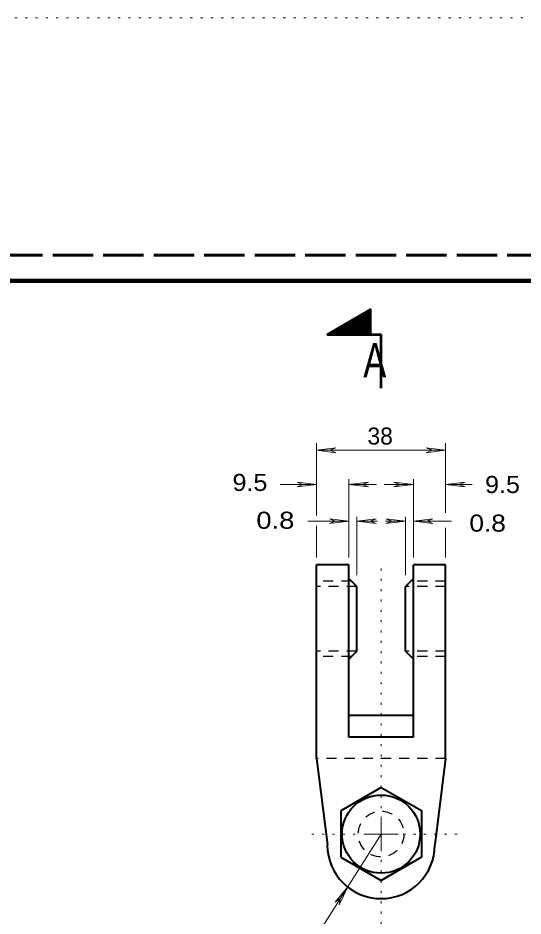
# Model space of a CAD drawing. Extents: x 312583 to 312854, y 144419 to 144597.
# Drawn here: x 312663.9 to 312686.4, y 144556.8 to 144596.78 of the extents above; entities that cross this region are included whole.
import ezdxf
from ezdxf.enums import TextEntityAlignment as Align

# ---------------------------------------------------------------- set-up
doc = ezdxf.new("R2010")
doc.units = 0
doc.header["$LTSCALE"] = 0.3
for name, pattern in [('DOTTED', [1.5, 0.3, -1.2]), ('LONG_DASHED', [7.5, 6, -1.5]), ('SHORT_DASHED', [2.7, 1.5, -1.2])]:
    doc.linetypes.add(name, pattern=pattern)
for name, color, linetype, lineweight in [('1', 7, 'Continuous', 40), ('2', 7, 'Continuous', 13), ('62', 7, 'DOTTED', 13), ('63', 7, 'LONG_DASHED', 60)]:
    doc.layers.add(name, color=color, linetype=linetype, lineweight=lineweight)

msp = doc.modelspace()

# ---------------------------------------------------------------- linework, layer by layer
at = {"layer": '1', "lineweight": 35}
for p, q in [((312679.3353, 144582.6879), (312678.929, 144583.4009)), ((312679.366, 144582.6879), (312678.9443, 144583.4162)), ((312679.3966, 144582.6879), (312678.9673, 144583.4316)), ((312679.4196, 144582.6956), (312678.9903, 144583.4392)), ((312679.4503, 144582.6956), (312679.0056, 144583.4546)), ((312679.4733, 144582.6879), (312679.0286, 144583.4622)), ((312679.504, 144582.6879), (312679.0516, 144583.4776)), ((312679.527, 144582.6879), (312679.067, 144583.4852)), ((312679.5576, 144582.6879), (312679.09, 144583.5006)), ((312679.5883, 144582.6879), (312679.113, 144583.5082)), ((312679.6036, 144582.7109), (312679.1283, 144583.5236)), ((312679.6036, 144582.7646), (312679.159, 144583.5312)), ((312679.6036, 144582.8029), (312679.1743, 144583.5466)), ((312679.6036, 144582.8566), (312679.1973, 144583.5542)), ((312679.6036, 144582.9026), (312679.2203, 144583.5696)), ((312679.6036, 144582.9486), (312679.2356, 144583.5849)), ((312679.6036, 144582.9946), (312679.2586, 144583.5926)), ((312679.6036, 144583.0482), (312679.2816, 144583.6079)), ((312679.6036, 144583.0942), (312679.297, 144583.6232)), ((312679.6036, 144583.1402), (312679.32, 144583.6309)), ((312679.6036, 144583.1939), (312679.3353, 144583.6462)), ((312679.6036, 144583.2399), (312679.3583, 144583.6539)), ((312679.6036, 144583.2859), (312679.3813, 144583.6692)), ((312679.6036, 144583.3396), (312679.3966, 144583.6769)), ((312679.6036, 144583.3856), (312679.4273, 144583.6922)), ((312679.6036, 144583.4316), (312679.4426, 144583.6999)), ((312679.6036, 144583.4776), (312679.4656, 144583.7152)), ((312679.6036, 144583.5312), (312679.4886, 144583.7229)), ((312679.6036, 144583.5696), (312679.504, 144583.7382)), ((312679.6036, 144583.6232), (312679.527, 144583.7459)), ((312679.6036, 144583.6692), (312679.55, 144583.7612)), ((312679.6036, 144583.7229), (312679.5653, 144583.7766)), ((312679.6036, 144583.7689), (312679.5883, 144583.7842)), ((312678.423, 144582.6879), (312678.239, 144583.0099)), ((312678.4536, 144582.6879), (312678.262, 144583.0176)), ((312678.4766, 144582.6879), (312678.285, 144583.0329)), ((312678.5073, 144582.6879), (312678.3003, 144583.0482)), ((312678.5303, 144582.6879), (312678.3233, 144583.0559)), ((312678.561, 144582.6879), (312678.3463, 144583.0712)), ((312678.5916, 144582.6879), (312678.3616, 144583.0866)), ((312678.6223, 144582.6879), (312678.3846, 144583.0942)), ((312678.6453, 144582.6879), (312678.4076, 144583.1096)), ((312678.6683, 144582.6879), (312678.4306, 144583.1172)), ((312678.699, 144582.6879), (312678.446, 144583.1326)), ((312678.7296, 144582.6879), (312678.469, 144583.1402)), ((312678.7526, 144582.6879), (312678.492, 144583.1556)), ((312678.7833, 144582.6879), (312678.5073, 144583.1632)), ((312678.814, 144582.6879), (312678.5303, 144583.1786)), ((312678.837, 144582.6879), (312678.5533, 144583.1862)), ((312678.8676, 144582.6879), (312678.5686, 144583.2016)), ((312678.8983, 144582.6879), (312678.5916, 144583.2092)), ((312678.9213, 144582.6879), (312678.6146, 144583.2246)), ((312678.952, 144582.6956), (312678.63, 144583.2399)), ((312678.975, 144582.6879), (312678.6606, 144583.2476)), ((312679.0056, 144582.6879), (312678.676, 144583.2629)), ((312679.0286, 144582.6879), (312678.699, 144583.2706)), ((312679.0593, 144582.6879), (312678.722, 144583.2859)), ((312679.09, 144582.6879), (312678.7373, 144583.2936)), ((312679.1206, 144582.6879), (312678.7603, 144583.3089)), ((312679.1436, 144582.6879), (312678.7833, 144583.3166)), ((312679.1666, 144582.6879), (312678.7986, 144583.3319)), ((312679.1973, 144582.6956), (312678.8216, 144583.3396)), ((312679.228, 144582.6879), (312678.8446, 144583.3549)), ((312679.251, 144582.6879), (312678.86, 144583.3626)), ((312679.2816, 144582.6879), (312678.883, 144583.3779)), ((312679.3123, 144582.6879), (312678.906, 144583.3932)), ((312677.7023, 144582.6879), (312677.7023, 144582.7032)), ((312677.733, 144582.6879), (312677.7253, 144582.7109)), ((312677.7636, 144582.6879), (312677.7406, 144582.7262)), ((312677.7866, 144582.6879), (312677.7636, 144582.7339)), ((312677.8173, 144582.6879), (312677.7866, 144582.7492)), ((312677.8403, 144582.6879), (312677.802, 144582.7569)), ((312677.871, 144582.6879), (312677.825, 144582.7722)), ((312677.9016, 144582.6879), (312677.848, 144582.7799)), ((312677.9323, 144582.6879), (312677.8633, 144582.7952)), ((312677.9553, 144582.6879), (312677.8863, 144582.8029)), ((312677.9783, 144582.6879), (312677.9093, 144582.8182)), ((312678.009, 144582.6879), (312677.9323, 144582.8259)), ((312678.032, 144582.6879), (312677.9476, 144582.8412)), ((312678.0626, 144582.6879), (312677.9706, 144582.8566)), ((312678.0933, 144582.6879), (312677.9936, 144582.8642)), ((312678.124, 144582.6879), (312678.009, 144582.8796)), ((312678.147, 144582.6879), (312678.032, 144582.8949)), ((312678.1776, 144582.6879), (312678.055, 144582.9026)), ((312678.2006, 144582.6879), (312678.0703, 144582.9179)), ((312678.2313, 144582.6879), (312678.0933, 144582.9256)), ((312678.262, 144582.6879), (312678.1163, 144582.9409)), ((312678.285, 144582.6879), (312678.1316, 144582.9486)), ((312678.3156, 144582.6879), (312678.1623, 144582.9639)), ((312678.3386, 144582.6879), (312678.1776, 144582.9716)), ((312678.3693, 144582.6879), (312678.2006, 144582.9869)), ((312678.4, 144582.6879), (312678.2236, 144582.9946))]:
    msp.add_line(p, q, dxfattribs=at)
at = {"layer": '1', "lineweight": 53}
for p in [(312679.6036, 144582.6879), (312680.079, 144580.2959), (312680.079, 144580.2959)]:
    msp.add_line(p, (312680.079, 144582.6879), dxfattribs=at)
at = {"layer": '1'}
for p, q in [((312677.204, 144563.8049), (312677.204, 144572.4299)), ((312678.6453, 144572.4299), (312677.204, 144572.4299)), ((312678.6453, 144564.7632), (312678.6453, 144572.4299)), ((312681.5203, 144564.7632), (312681.5203, 144572.4299)), ((312682.954, 144572.4299), (312681.5203, 144572.4299)), ((312682.954, 144563.8049), (312682.954, 144572.4299)), ((312678.998, 144571.4716), (312678.6453, 144571.8242)), ((312681.5203, 144571.8242), (312681.16, 144571.4639)), ((312678.998, 144568.5889), (312678.998, 144571.4716)), ((312681.16, 144568.5966), (312681.16, 144571.4639)), ((312678.998, 144568.5889), (312678.6453, 144568.2286)), ((312681.5203, 144568.2362), (312681.16, 144568.5966)), ((312681.5203, 144565.7216), (312678.6453, 144565.7216)), ((312681.5203, 144564.7632), (312678.6453, 144564.7632)), ((312677.204, 144563.8049), (312677.687, 144559.9716)), ((312682.954, 144563.8049), (312682.4786, 144559.9716)), ((312680.0866, 144562.5246), (312678.285, 144561.4819)), ((312680.0866, 144562.5246), (312681.8806, 144561.4896)), ((312678.285, 144561.4819), (312678.285, 144559.4119)), ((312681.8806, 144561.4896), (312681.8806, 144559.4119)), ((312678.285, 144559.4119), (312680.0866, 144558.3769)), ((312681.8806, 144559.4119), (312680.0866, 144558.3769))]:
    msp.add_line(p, q, dxfattribs=at)
at = {"layer": '1', "linetype": 'SHORT_DASHED', "lineweight": 25}
for p, q in [((312678.7603, 144571.7016), (312677.204, 144571.7016)), ((312678.998, 144571.4639), (312677.204, 144571.4639)), ((312682.954, 144571.4639), (312681.16, 144571.4639)), ((312682.954, 144571.7016), (312681.3976, 144571.7016)), ((312678.998, 144568.5889), (312677.204, 144568.5889)), ((312678.7603, 144568.3512), (312677.204, 144568.3512)), ((312682.954, 144568.5889), (312681.16, 144568.5889)), ((312682.954, 144568.3512), (312681.3976, 144568.3512)), ((312682.954, 144563.8049), (312677.204, 144563.8049))]:
    msp.add_line(p, q, dxfattribs=at)
at = {"layer": '1', "lineweight": 158}
msp.add_lwpolyline([(312616.5, 144423.1446), (312616.5, 144585.0846), (312849, 144585.0846)], dxfattribs=at)
at = {"layer": '1', "lineweight": 53}
msp.add_lwpolyline([(312679.6036, 144582.6879), (312679.6036, 144583.7996), (312677.687, 144582.6879)], close=True, dxfattribs=at)
at = {"layer": '1'}
msp.add_circle((312680.079, 144560.4469), 1.7394, dxfattribs=at)
at = {"layer": '1', "linetype": 'SHORT_DASHED', "lineweight": 25}
msp.add_circle((312680.079, 144560.4469), 1.0182, dxfattribs=at)
at = {"layer": '1'}
msp.add_arc((312680.079, 144559.9677), 2.3958, 180, 0, dxfattribs=at)
at = {"layer": '2'}
for p, q in [((312677.204, 144574.6379), (312677.204, 144577.8579)), ((312682.954, 144574.7529), (312682.954, 144577.8579)), ((312677.204, 144577.5359), (312678.0703, 144577.6432)), ((312677.204, 144577.5359), (312682.954, 144577.5359)), ((312677.204, 144577.5359), (312678.0703, 144577.4286)), ((312678.0703, 144577.6432), (312677.7943, 144577.5359)), ((312678.0703, 144577.4286), (312677.7943, 144577.5359)), ((312682.0876, 144577.6432), (312682.3636, 144577.5359)), ((312682.954, 144577.5359), (312682.0876, 144577.6432)), ((312682.0876, 144577.4286), (312682.3636, 144577.5359)), ((312682.954, 144577.5359), (312682.0876, 144577.4286)), ((312678.6453, 144572.7672), (312678.6453, 144576.2479)), ((312681.5203, 144572.7672), (312681.5203, 144576.2479)), ((312675.5863, 144576.0102), (312677.204, 144576.0102)), ((312676.3376, 144576.1176), (312676.6136, 144576.0102)), ((312677.204, 144576.0102), (312676.3376, 144576.1176)), ((312676.3376, 144575.9029), (312676.6136, 144576.0102)), ((312677.204, 144576.0102), (312676.3376, 144575.9029)), ((312678.6453, 144576.0102), (312679.5116, 144576.1176)), ((312678.6453, 144576.0102), (312679.872, 144576.0102)), ((312678.6453, 144576.0102), (312679.5116, 144575.9029)), ((312679.5116, 144576.1176), (312679.2356, 144576.0102)), ((312679.5116, 144575.9029), (312679.2356, 144576.0102)), ((312680.217, 144576.0102), (312681.5203, 144576.0102)), ((312680.654, 144576.1176), (312680.93, 144576.0102)), ((312681.5203, 144576.0102), (312680.654, 144576.1176)), ((312680.654, 144575.9029), (312680.93, 144576.0102)), ((312681.5203, 144576.0102), (312680.654, 144575.9029)), ((312682.954, 144576.0102), (312683.8203, 144576.1176)), ((312682.954, 144576.0102), (312684.1423, 144576.0102)), ((312682.954, 144576.0102), (312683.8203, 144575.9029)), ((312683.8203, 144576.1176), (312683.5443, 144576.0102)), ((312683.8203, 144575.9029), (312683.5443, 144576.0102)), ((312676.8206, 144574.3772), (312678.6453, 144574.3772)), ((312677.779, 144574.4846), (312678.055, 144574.3772)), ((312678.6453, 144574.3772), (312677.779, 144574.4846)), ((312677.779, 144574.2699), (312678.055, 144574.3772)), ((312678.6453, 144574.3772), (312677.779, 144574.2699)), ((312678.998, 144571.9699), (312678.998, 144574.5766)), ((312678.998, 144574.3772), (312679.8643, 144574.4846)), ((312678.998, 144574.3772), (312679.9026, 144574.3772)), ((312678.998, 144574.3772), (312679.8643, 144574.2699)), ((312679.8643, 144574.4846), (312679.5883, 144574.3772)), ((312679.8643, 144574.2699), (312679.5883, 144574.3772)), ((312680.2783, 144574.3772), (312681.16, 144574.3772)), ((312680.2936, 144574.4846), (312680.5696, 144574.3772)), ((312681.16, 144574.3772), (312680.2936, 144574.4846)), ((312680.2936, 144574.2699), (312680.5696, 144574.3772)), ((312681.16, 144574.3772), (312680.2936, 144574.2699)), ((312681.16, 144571.9699), (312681.16, 144574.5766)), ((312681.5203, 144574.3772), (312682.3866, 144574.4846)), ((312681.5203, 144574.3772), (312683.2146, 144574.3772)), ((312681.5203, 144574.3772), (312682.3866, 144574.2699)), ((312682.3866, 144574.4846), (312682.1106, 144574.3772)), ((312682.3866, 144574.2699), (312682.1106, 144574.3772)), ((312677.204, 144572.7672), (312677.204, 144574.1779)), ((312682.954, 144572.7672), (312682.954, 144574.0859)), ((312680.079, 144560.4469), (312680.079, 144561.2136)), ((312680.079, 144560.4469), (312675.6783, 144553.4932)), ((312680.079, 144560.4469), (312679.3123, 144560.4469)), ((312680.079, 144560.4469), (312680.079, 144559.6802)), ((312680.079, 144560.4469), (312680.8456, 144560.4469)), ((312678.5916, 144558.0932), (312678.032, 144557.4186)), ((312678.5916, 144558.0932), (312678.216, 144557.3036)), ((312678.032, 144557.4186), (312678.2773, 144557.5949)), ((312678.216, 144557.3036), (312678.2773, 144557.5949))]:
    msp.add_line(p, q, dxfattribs=at)
at = {"layer": '2', "linetype": 'DOTTED'}
for p, q in [((312680.079, 144561.5969), (312680.079, 144572.4299)), ((312678.929, 144560.4469), (312676.6366, 144560.4469)), ((312681.068, 144560.4469), (312683.5443, 144560.4469)), ((312680.079, 144559.2969), (312680.079, 144556.2916))]:
    msp.add_line(p, q, dxfattribs=at)
at = {"layer": '62'}
msp.add_line((312601.2, 144596.7846), (312853.5, 144596.7846), dxfattribs=at)
at = {"layer": '63'}
msp.add_line((312851.75, 144586.2246), (312583.526, 144586.2246), dxfattribs=at)

# ---------------------------------------------------------------- texts
at = {"layer": '1', "width": 0.75}
msp.add_text('A', height=1.533, dxfattribs=at).set_placement((312679.7991, 144580.7789), align=Align.CENTER)
at = {"layer": '2'}
msp.add_text('38', height=0.76, dxfattribs=at).set_placement((312679.4735, 144577.7898))
for s, width, p in [('9.5', 1.1, (312673.4604, 144575.7237)), ('9.5', 1.1, (312684.7111, 144575.6316)), ('0.8 ', 1.2, (312674.522, 144574.0409)), ('0.8', 1.15, (312684.013, 144573.9124))]:
    msp.add_text(s, height=0.76, dxfattribs=dict(at, width=width)).set_placement(p)

doc.saveas('drawing.dxf')
